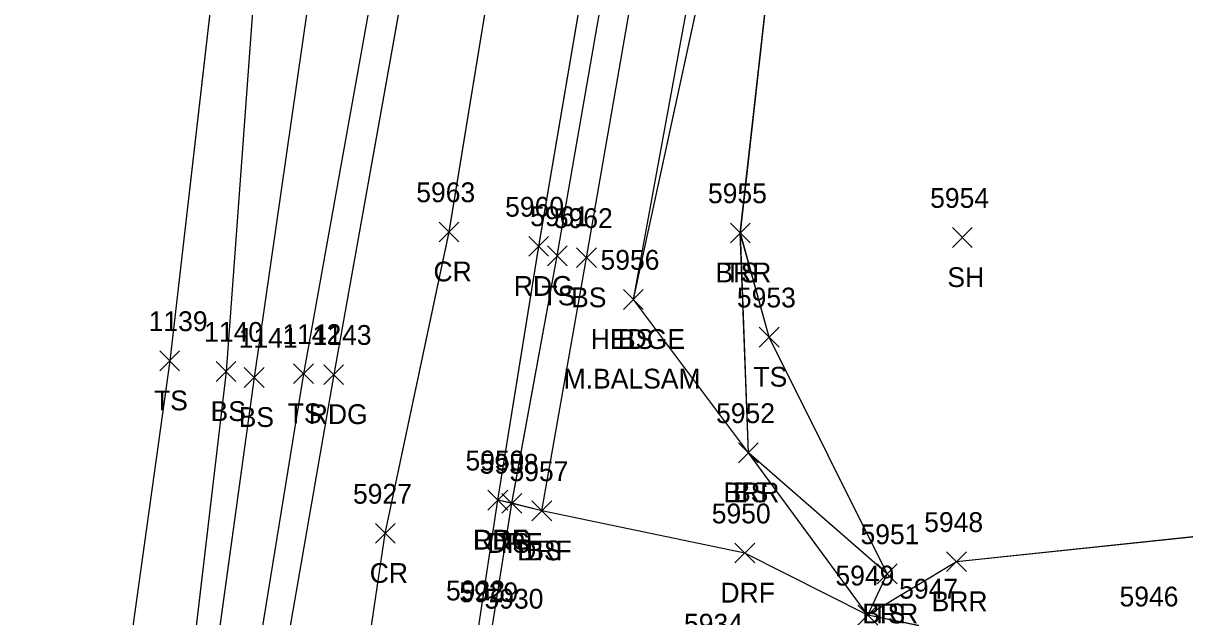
# Model space of a CAD drawing. Extents: x 1554668 to 1563881, y 831386 to 834374.
# Drawn here: x 1561871.6 to 1561988.8, y 833935.7 to 833995.6 of the extents above; entities that cross this region are included whole.
import ezdxf

# ---------------------------------------------------------------- set-up
doc = ezdxf.new("R2010")
doc.units = 0
for name, color, linetype in [('L_A', 7, 'Continuous'), ('L_C', 7, 'Continuous'), ('L_I', 7, 'Continuous'), ('L_TIC', 7, 'Continuous'), ('LABL', 7, 'Continuous'), ('LAHR', 7, 'Continuous'), ('LELB', 7, 'Continuous'), ('P_A', 7, 'Continuous'), ('P_I', 7, 'Continuous'), ('P_TIC', 7, 'Continuous'), ('PEU', 7, 'Continuous'), ('PRC', 7, 'Continuous'), ('R_A', 7, 'Continuous'), ('R_I', 7, 'Continuous'), ('R_TIC', 7, 'Continuous'), ('RDF', 7, 'Continuous')]:
    doc.layers.add(name, color=color, linetype=linetype)

msp = doc.modelspace()

# ---------------------------------------------------------------- linework, layer by layer
at = {"layer": 'L_TIC'}
for points in [[(1561942.96, 833973.43), (1561944.96, 833975.43)], [(1561944.96, 833973.43), (1561942.96, 833975.43)], [(1561942.96, 833973.43), (1561944.96, 833975.43)], [(1561944.96, 833973.43), (1561942.96, 833975.43)], [(1561965.38, 833972.96), (1561967.38, 833974.96)], [(1561967.38, 833972.96), (1561965.38, 833974.96)], [(1561924.49, 833971.11), (1561926.49, 833973.11)], [(1561926.49, 833971.11), (1561924.49, 833973.11)], [(1561927.44, 833970.92), (1561929.44, 833972.92)], [(1561929.44, 833970.92), (1561927.44, 833972.92)], [(1561932.17, 833966.71), (1561934.17, 833968.71)], [(1561934.17, 833966.71), (1561932.17, 833968.71)], [(1561932.17, 833966.71), (1561934.17, 833968.71)], [(1561934.17, 833966.71), (1561932.17, 833968.71)], [(1561945.88, 833962.9), (1561947.88, 833964.9)], [(1561947.88, 833962.9), (1561945.88, 833964.9)], [(1561885.36, 833960.51), (1561887.36, 833962.51)], [(1561887.36, 833960.51), (1561885.36, 833962.51)], [(1561891.04, 833959.43), (1561893.04, 833961.43)], [(1561893.04, 833959.43), (1561891.04, 833961.43)], [(1561893.88, 833958.83), (1561895.88, 833960.83)], [(1561895.88, 833958.83), (1561893.88, 833960.83)], [(1561898.86, 833959.21), (1561900.86, 833961.21)], [(1561900.86, 833959.21), (1561898.86, 833961.21)], [(1561943.78, 833951.22), (1561945.78, 833953.22)], [(1561945.78, 833951.22), (1561943.78, 833953.22)], [(1561943.78, 833951.22), (1561945.78, 833953.22)], [(1561945.78, 833951.22), (1561943.78, 833953.22)], [(1561919.9, 833946.11), (1561921.9, 833948.11)], [(1561921.9, 833946.11), (1561919.9, 833948.11)], [(1561922.92, 833945.36), (1561924.92, 833947.36)], [(1561924.92, 833945.36), (1561922.92, 833947.36)], [(1561964.79, 833940.22), (1561966.79, 833942.22)], [(1561966.79, 833940.22), (1561964.79, 833942.22)], [(1561957.79, 833938.99), (1561959.79, 833940.99)], [(1561959.79, 833938.99), (1561957.79, 833940.99)], [(1561957.79, 833938.99), (1561959.79, 833940.99)], [(1561959.79, 833938.99), (1561957.79, 833940.99)], [(1561955.84, 833934.82), (1561957.84, 833936.82)], [(1561957.84, 833934.82), (1561955.84, 833936.82)], [(1561955.84, 833934.82), (1561957.84, 833936.82)], [(1561957.84, 833934.82), (1561955.84, 833936.82)]]:
    msp.add_lwpolyline(points, dxfattribs=at)
at = {"layer": 'LABL'}
for points in [[(1562011.76, 833940.83), (1561992.19, 833943.99), (1561965.79, 833941.22), (1561956.84, 833935.82), (1561958.79, 833939.99), (1561944.78, 833952.22), (1561943.96, 833974.43), (1561948.54, 834015.15), (1561964.21, 834009.16), (1561972.84, 834001.4)], [(1562011.76, 833940.83), (1561992.19, 833943.98), (1561965.8, 833941.22), (1561956.84, 833935.82), (1561958.79, 833939.99), (1561944.79, 833952.22), (1561943.97, 833974.42), (1561948.54, 834015.15), (1561964.21, 834009.16), (1561972.84, 834001.4)], [(1562011.76, 833940.83), (1561992.19, 833943.98), (1561965.8, 833941.22), (1561956.84, 833935.82), (1561958.79, 833939.99), (1561944.79, 833952.22), (1561943.97, 833974.42), (1561948.54, 834015.15), (1561964.21, 834009.16), (1561972.84, 834001.4)], [(1562011.76, 833940.83), (1561992.19, 833943.98), (1561965.8, 833941.22), (1561956.84, 833935.82), (1561958.79, 833939.99), (1561944.79, 833952.22), (1561943.97, 833974.42), (1561948.54, 834015.15), (1561964.21, 834009.16), (1561972.84, 834001.4)]]:
    msp.add_lwpolyline(points, dxfattribs=at)
at = {"layer": 'LAHR'}
for points in [[(1561933.17, 833967.71), (1561943.92, 834017.24), (1561949.01, 834047.56), (1561954.45, 834088.78), (1561954.61, 834109.86), (1561954.6, 834110.79), (1561958.24, 834120.47)], [(1561933.17, 833967.71), (1561943.92, 834017.24), (1561949.01, 834047.56), (1561954.45, 834088.78), (1561954.61, 834109.86), (1561954.6, 834110.79), (1561958.24, 834120.47)], [(1561933.17, 833967.71), (1561943.92, 834017.24), (1561949.01, 834047.56), (1561954.45, 834088.78), (1561954.61, 834109.86), (1561954.6, 834110.79), (1561958.24, 834120.47)], [(1561933.17, 833967.71), (1561943.91, 834017.25), (1561949.02, 834047.56), (1561954.45, 834088.78), (1561954.61, 834109.86), (1561954.6, 834110.79), (1561958.24, 834120.47)]]:
    msp.add_lwpolyline(points, dxfattribs=at)
at = {"layer": 'LELB'}
for points in [[(1561890.59, 833773.39), (1561895.72, 833803.09), (1561903.04, 833845.23), (1561912.56, 833892.47), (1561912.52, 833900.11), (1561918.86, 833934.14), (1561920.9, 833947.12), (1561925.49, 833972.11), (1561933.78, 834019.88), (1561938.56, 834049.2), (1561945.5, 834091.94), (1561950.38, 834111.94), (1561953.62, 834113.33), (1561954.6, 834110.79), (1561955.4, 834117.28), (1561954.74, 834122.9), (1561961.07, 834128.41)], [(1561890.59, 833773.39), (1561895.72, 833803.09), (1561903.04, 833845.23), (1561912.56, 833892.47), (1561912.52, 833900.11), (1561918.86, 833934.14), (1561920.9, 833947.12), (1561925.49, 833972.11), (1561933.78, 834019.88), (1561938.56, 834049.2), (1561945.5, 834091.94), (1561950.38, 834111.94), (1561953.62, 834113.33), (1561954.6, 834110.79), (1561955.4, 834117.28), (1561954.74, 834122.9), (1561961.07, 834128.41)], [(1561890.59, 833773.39), (1561895.72, 833803.09), (1561903.04, 833845.23), (1561912.56, 833892.47), (1561912.52, 833900.11), (1561918.86, 833934.14), (1561920.9, 833947.12), (1561925.49, 833972.11), (1561933.78, 834019.88), (1561938.56, 834049.2), (1561945.5, 834091.94), (1561950.38, 834111.94), (1561953.62, 834113.33), (1561954.6, 834110.79), (1561955.4, 834117.28), (1561954.74, 834122.9), (1561961.07, 834128.41)], [(1561890.59, 833773.39), (1561895.72, 833803.08), (1561903.04, 833845.23), (1561912.56, 833892.47), (1561912.52, 833900.11), (1561918.86, 833934.13), (1561920.9, 833947.11), (1561925.49, 833972.11), (1561933.78, 834019.88), (1561938.56, 834049.2), (1561945.51, 834091.94), (1561950.38, 834111.94), (1561953.62, 834113.33), (1561954.6, 834110.79), (1561955.4, 834117.28), (1561954.73, 834122.9), (1561961.07, 834128.41)], [(1561923.92, 833946.36), (1561928.44, 833971.92), (1561936.65, 834019.21), (1561937.56, 834020.45), (1561941.76, 834048.64), (1561947.35, 834092.26), (1561953.88, 834111.21), (1561953.62, 834113.33), (1561951.9, 834118.24), (1561953.54, 834128.25)], [(1561923.92, 833946.36), (1561928.44, 833971.92), (1561936.65, 834019.21), (1561937.56, 834020.45), (1561941.76, 834048.64), (1561947.35, 834092.26), (1561953.88, 834111.21), (1561953.62, 834113.33), (1561951.9, 834118.24), (1561953.54, 834128.25)], [(1561923.92, 833946.36), (1561928.44, 833971.92), (1561936.65, 834019.21), (1561937.56, 834020.45), (1561941.76, 834048.64), (1561947.35, 834092.26), (1561953.88, 834111.21), (1561953.62, 834113.33), (1561951.9, 834118.24), (1561953.54, 834128.25)], [(1561923.92, 833946.36), (1561928.44, 833971.92), (1561936.65, 834019.21), (1561937.55, 834020.45), (1561941.75, 834048.64), (1561947.35, 834092.26), (1561953.88, 834111.21), (1561953.62, 834113.33), (1561951.9, 834118.24), (1561953.54, 834128.25)], [(1561956.84, 833935.82), (1561944.79, 833952.22), (1561933.17, 833967.71), (1561942.4, 834017.99), (1561945.38, 834048.68), (1561950.34, 834090.54), (1561954.61, 834109.86), (1561953.88, 834111.21)], [(1561956.84, 833935.82), (1561944.79, 833952.22), (1561933.17, 833967.71), (1561942.4, 834017.99), (1561945.38, 834048.68), (1561950.34, 834090.54), (1561954.61, 834109.86), (1561953.88, 834111.21)], [(1561956.84, 833935.82), (1561944.79, 833952.22), (1561933.17, 833967.71), (1561942.4, 834017.99), (1561945.38, 834048.68), (1561950.34, 834090.54), (1561954.61, 834109.86), (1561953.88, 834111.21)], [(1561956.84, 833935.82), (1561944.78, 833952.22), (1561933.17, 833967.71), (1561942.4, 834017.99), (1561945.38, 834048.68), (1561950.34, 834090.54), (1561954.61, 834109.86), (1561953.88, 834111.21)], [(1561815.74, 834086.46), (1561830.54, 834078.7), (1561857.36, 834066.17), (1561882.7, 834039.77), (1561887.42, 834039.12), (1561893.22, 834026.09), (1561901.9, 834008.43), (1561894.88, 833959.83), (1561888.21, 833911.57), (1561878.88, 833861.26), (1561873.84, 833826.24), (1561871.32, 833811.79), (1561866.2, 833788.52), (1561864.7, 833787.61), (1561863.71, 833789.64)], [(1561815.74, 834086.46), (1561831.97, 834080.43), (1561858.23, 834067.96), (1561883.25, 834047.53), (1561891.65, 834042.46), (1561901.6, 834025.45), (1561908.82, 834010.15), (1561899.86, 833960.21), (1561892.01, 833911.96), (1561883.18, 833863.91), (1561875.73, 833824.99), (1561873.41, 833811.32), (1561868.97, 833788.78), (1561866.02, 833786.68), (1561862.5, 833787.34), (1561864.02, 833802.29)], [(1561815.74, 834086.46), (1561830.54, 834078.7), (1561857.36, 834066.17), (1561882.7, 834039.77), (1561887.42, 834039.12), (1561893.22, 834026.09), (1561901.9, 834008.43), (1561894.88, 833959.83), (1561888.21, 833911.57), (1561878.88, 833861.26), (1561873.84, 833826.24), (1561871.32, 833811.79), (1561866.2, 833788.52), (1561864.7, 833787.61), (1561863.71, 833789.64)], [(1561815.74, 834086.46), (1561831.97, 834080.43), (1561858.23, 834067.96), (1561883.25, 834047.53), (1561891.65, 834042.46), (1561901.6, 834025.45), (1561908.82, 834010.15), (1561899.86, 833960.21), (1561892.01, 833911.96), (1561883.18, 833863.91), (1561875.73, 833824.99), (1561873.41, 833811.32), (1561868.97, 833788.78), (1561866.02, 833786.68), (1561862.5, 833787.34), (1561864.02, 833802.29)], [(1561815.74, 834086.46), (1561830.54, 834078.7), (1561857.36, 834066.17), (1561882.7, 834039.77), (1561887.42, 834039.12), (1561893.22, 834026.09), (1561901.9, 834008.43), (1561894.88, 833959.83), (1561888.21, 833911.57), (1561878.88, 833861.26), (1561873.84, 833826.24), (1561871.32, 833811.79), (1561866.2, 833788.52), (1561864.7, 833787.61), (1561863.71, 833789.64)], [(1561815.74, 834086.46), (1561831.97, 834080.43), (1561858.23, 834067.96), (1561883.25, 834047.53), (1561891.65, 834042.46), (1561901.6, 834025.45), (1561908.82, 834010.15), (1561899.86, 833960.21), (1561892.01, 833911.96), (1561883.18, 833863.91), (1561875.73, 833824.99), (1561873.41, 833811.32), (1561868.97, 833788.78), (1561866.02, 833786.68), (1561862.5, 833787.34), (1561864.02, 833802.29)], [(1561815.74, 834086.46), (1561830.54, 834078.7), (1561857.37, 834066.17), (1561882.7, 834039.77), (1561887.42, 834039.12), (1561893.22, 834026.09), (1561901.9, 834008.43), (1561894.88, 833959.83), (1561888.22, 833911.56), (1561878.88, 833861.26), (1561873.84, 833826.25), (1561871.32, 833811.8), (1561866.2, 833788.52), (1561864.7, 833787.61), (1561863.71, 833789.64)], [(1561815.74, 834086.46), (1561831.97, 834080.43), (1561858.23, 834067.96), (1561883.25, 834047.53), (1561891.65, 834042.46), (1561901.6, 834025.45), (1561908.82, 834010.15), (1561899.86, 833960.21), (1561892.01, 833911.96), (1561883.18, 833863.91), (1561875.73, 833824.99), (1561873.41, 833811.33), (1561868.97, 833788.78), (1561866.02, 833786.68), (1561862.5, 833787.34), (1561864.02, 833802.28)], [(1561853.22, 834063.56), (1561878.87, 834036.97), (1561887.19, 834023.31), (1561895.32, 834005.06), (1561892.04, 833960.44), (1561886.33, 833911.87), (1561875.09, 833862.64), (1561871.37, 833827.19), (1561868.33, 833813.19), (1561863.71, 833789.64)], [(1561853.22, 834063.56), (1561877.74, 834034.87), (1561883, 834019.83), (1561891.11, 834002.8), (1561886.36, 833961.51), (1561879.68, 833913.48), (1561869.91, 833864.41), (1561866.18, 833828.25), (1561865.19, 833815.47), (1561863.21, 833805.57), (1561864.02, 833802.29)], [(1561853.22, 834063.56), (1561878.87, 834036.97), (1561887.19, 834023.31), (1561895.32, 834005.06), (1561892.04, 833960.44), (1561886.33, 833911.87), (1561875.09, 833862.64), (1561871.37, 833827.19), (1561868.33, 833813.19), (1561863.71, 833789.64)], [(1561853.22, 834063.56), (1561877.74, 834034.87), (1561883, 834019.83), (1561891.11, 834002.8), (1561886.36, 833961.51), (1561879.68, 833913.48), (1561869.91, 833864.41), (1561866.18, 833828.25), (1561865.19, 833815.47), (1561863.21, 833805.57), (1561864.02, 833802.29)], [(1561853.22, 834063.56), (1561878.87, 834036.97), (1561887.19, 834023.31), (1561895.32, 834005.06), (1561892.04, 833960.44), (1561886.33, 833911.87), (1561875.09, 833862.64), (1561871.37, 833827.19), (1561868.33, 833813.19), (1561863.71, 833789.64)], [(1561853.22, 834063.56), (1561877.74, 834034.87), (1561883, 834019.83), (1561891.11, 834002.8), (1561886.36, 833961.51), (1561879.68, 833913.48), (1561869.91, 833864.41), (1561866.18, 833828.25), (1561865.19, 833815.47), (1561863.21, 833805.57), (1561864.02, 833802.29)], [(1561853.22, 834063.56), (1561878.87, 834036.97), (1561887.19, 834023.32), (1561895.32, 834005.06), (1561892.04, 833960.43), (1561886.33, 833911.86), (1561875.09, 833862.64), (1561871.37, 833827.19), (1561868.33, 833813.19), (1561863.71, 833789.64)], [(1561853.22, 834063.56), (1561877.74, 834034.87), (1561883, 834019.83), (1561891.11, 834002.81), (1561886.36, 833961.51), (1561879.68, 833913.48), (1561869.91, 833864.41), (1561866.18, 833828.24), (1561865.19, 833815.47), (1561863.21, 833805.57), (1561864.02, 833802.28)], [(1561958.79, 833939.99), (1561946.88, 833963.9), (1561943.96, 833974.43)], [(1561958.79, 833939.99), (1561946.89, 833963.9), (1561943.97, 833974.42)], [(1561958.79, 833939.99), (1561946.89, 833963.9), (1561943.97, 833974.42)], [(1561958.79, 833939.99), (1561946.89, 833963.9), (1561943.97, 833974.42)]]:
    msp.add_lwpolyline(points, dxfattribs=at)
at = {"layer": 'P_TIC'}
for points in [[(1561913.56, 833973.53), (1561915.56, 833975.53)], [(1561915.56, 833973.53), (1561913.56, 833975.53)], [(1561922.61, 833972.07), (1561924.61, 833974.07)], [(1561924.61, 833972.07), (1561922.61, 833974.07)], [(1561901.91, 833959.12), (1561903.91, 833961.12)], [(1561903.91, 833959.12), (1561901.91, 833961.12)], [(1561918.49, 833946.44), (1561920.49, 833948.44)], [(1561920.49, 833946.44), (1561918.49, 833948.44)], [(1561907.12, 833943.08), (1561909.12, 833945.08)], [(1561909.12, 833943.08), (1561907.12, 833945.08)]]:
    msp.add_lwpolyline(points, dxfattribs=at)
at = {"layer": 'PEU'}
for points in [[(1561919.94, 834298.23), (1561943.28, 834270.95), (1561951.49, 834242.5), (1561947.43, 834199.98), (1561938.33, 834160.95), (1561930.99, 834108.21), (1561926.2, 834084.15), (1561918.63, 834048.82), (1561911.3, 834007.02), (1561902.91, 833960.12), (1561894.33, 833910.71), (1561885.39, 833863.27), (1561878.37, 833822.84), (1561871.83, 833787.48), (1561866.71, 833759.34), (1561861.91, 833735.82)], [(1561919.94, 834298.23), (1561943.28, 834270.95), (1561951.49, 834242.5), (1561947.43, 834199.98), (1561938.33, 834160.95), (1561930.99, 834108.21), (1561926.2, 834084.15), (1561918.63, 834048.82), (1561911.3, 834007.02), (1561902.91, 833960.12), (1561894.33, 833910.71), (1561885.39, 833863.27), (1561878.37, 833822.84), (1561871.83, 833787.48), (1561866.71, 833759.34), (1561861.91, 833735.82)], [(1561919.94, 834298.23), (1561943.28, 834270.95), (1561951.49, 834242.5), (1561947.43, 834199.98), (1561938.33, 834160.95), (1561930.99, 834108.21), (1561926.2, 834084.15), (1561918.63, 834048.82), (1561911.3, 834007.02), (1561902.91, 833960.12), (1561894.33, 833910.71), (1561885.39, 833863.27), (1561878.37, 833822.84), (1561871.83, 833787.48), (1561866.71, 833759.34), (1561861.91, 833735.82)], [(1561919.94, 834298.23), (1561943.28, 834270.95), (1561951.49, 834242.5), (1561947.43, 834199.98), (1561938.34, 834160.95), (1561930.99, 834108.21), (1561926.2, 834084.15), (1561918.63, 834048.82), (1561911.3, 834007.01), (1561902.91, 833960.12), (1561894.33, 833910.71), (1561885.39, 833863.26), (1561878.37, 833822.84), (1561871.83, 833787.48), (1561866.71, 833759.34), (1561861.91, 833735.82)], [(1561874.55, 833715.87), (1561887.48, 833772.58), (1561893.31, 833803.99), (1561901.36, 833845.45), (1561909.68, 833892.69), (1561910.73, 833900.62), (1561917.51, 833934.31), (1561919.49, 833947.44), (1561923.61, 833973.08), (1561931.59, 834020), (1561935.39, 834050.31), (1561943.17, 834094.38), (1561948.42, 834126.58), (1561953.28, 834146.88), (1561956.68, 834158.88)], [(1561874.55, 833715.87), (1561887.48, 833772.58), (1561893.31, 833803.99), (1561901.36, 833845.45), (1561909.68, 833892.69), (1561910.73, 833900.62), (1561917.51, 833934.31), (1561919.49, 833947.44), (1561923.61, 833973.08), (1561931.59, 834020), (1561935.39, 834050.31), (1561943.17, 834094.38), (1561948.42, 834126.58), (1561953.28, 834146.88), (1561956.68, 834158.88)], [(1561874.55, 833715.87), (1561887.48, 833772.58), (1561893.31, 833803.99), (1561901.36, 833845.45), (1561909.68, 833892.69), (1561910.73, 833900.62), (1561917.51, 833934.31), (1561919.49, 833947.44), (1561923.61, 833973.08), (1561931.59, 834020), (1561935.39, 834050.31), (1561943.17, 834094.38), (1561948.42, 834126.58), (1561953.28, 834146.88), (1561956.68, 834158.88)], [(1561874.55, 833715.88), (1561887.48, 833772.58), (1561893.31, 833803.99), (1561901.36, 833845.45), (1561909.68, 833892.69), (1561910.73, 833900.62), (1561917.51, 833934.31), (1561919.49, 833947.44), (1561923.61, 833973.07), (1561931.59, 834020), (1561935.39, 834050.31), (1561943.17, 834094.38), (1561948.42, 834126.57), (1561953.28, 834146.88), (1561956.68, 834158.88)]]:
    msp.add_lwpolyline(points, dxfattribs=at)
at = {"layer": 'PRC'}
for points in [[(1561800.21, 833371.54), (1561806.44, 833405.19), (1561812.66, 833434.93), (1561820.13, 833472.18), (1561827.53, 833505.74), (1561836.94, 833558.6), (1561848.04, 833617.29), (1561858.18, 833669.76), (1561866.96, 833717.24), (1561878.61, 833773.78), (1561885.02, 833806.83), (1561891.66, 833847.81), (1561899.78, 833893.72), (1561902.02, 833902.92), (1561908.12, 833944.07), (1561914.56, 833974.52), (1561922.25, 834021.37), (1561927.37, 834052.03), (1561935.21, 834096), (1561945.53, 834150.77)], [(1561800.21, 833371.54), (1561806.44, 833405.19), (1561812.66, 833434.93), (1561820.13, 833472.18), (1561827.53, 833505.74), (1561836.94, 833558.6), (1561848.04, 833617.29), (1561858.18, 833669.76), (1561866.96, 833717.24), (1561878.61, 833773.78), (1561885.02, 833806.83), (1561891.66, 833847.81), (1561899.78, 833893.72), (1561902.02, 833902.92), (1561908.12, 833944.07), (1561914.56, 833974.52), (1561922.25, 834021.37), (1561927.37, 834052.03), (1561935.21, 834096), (1561945.53, 834150.77)], [(1561800.21, 833371.54), (1561806.44, 833405.19), (1561812.66, 833434.93), (1561820.13, 833472.18), (1561827.53, 833505.74), (1561836.94, 833558.6), (1561848.04, 833617.29), (1561858.18, 833669.76), (1561866.96, 833717.24), (1561878.61, 833773.78), (1561885.02, 833806.83), (1561891.66, 833847.81), (1561899.78, 833893.72), (1561902.02, 833902.92), (1561908.12, 833944.07), (1561914.56, 833974.52), (1561922.25, 834021.37), (1561927.37, 834052.03), (1561935.21, 834096), (1561945.53, 834150.77)], [(1561800.21, 833371.54), (1561806.44, 833405.19), (1561812.65, 833434.93), (1561820.13, 833472.19), (1561827.53, 833505.75), (1561836.94, 833558.61), (1561848.04, 833617.29), (1561858.18, 833669.76), (1561866.96, 833717.25), (1561878.6, 833773.78), (1561885.02, 833806.83), (1561891.66, 833847.81), (1561899.78, 833893.72), (1561902.02, 833902.92), (1561908.12, 833944.08), (1561914.56, 833974.53), (1561922.25, 834021.37), (1561927.37, 834052.03), (1561935.21, 834096), (1561945.53, 834150.77)]]:
    msp.add_lwpolyline(points, dxfattribs=at)
at = {"layer": 'R_TIC'}
for points in [[(1561918.49, 833946.44), (1561920.49, 833948.44)], [(1561920.49, 833946.44), (1561918.49, 833948.44)], [(1561919.9, 833946.11), (1561921.9, 833948.11)], [(1561921.9, 833946.11), (1561919.9, 833948.11)], [(1561922.92, 833945.36), (1561924.92, 833947.36)], [(1561924.92, 833945.36), (1561922.92, 833947.36)], [(1561943.42, 833941.09), (1561945.42, 833943.09)], [(1561945.42, 833941.09), (1561943.42, 833943.09)], [(1561955.84, 833934.82), (1561957.84, 833936.82)], [(1561957.84, 833934.82), (1561955.84, 833936.82)]]:
    msp.add_lwpolyline(points, dxfattribs=at)
at = {"layer": 'RDF'}
for points in [[(1561985.57, 833933.7), (1561963.27, 833934.5), (1561956.84, 833935.82), (1561944.43, 833942.09), (1561923.92, 833946.36), (1561920.9, 833947.12), (1561919.49, 833947.44)], [(1561985.57, 833933.7), (1561963.27, 833934.5), (1561956.84, 833935.82), (1561944.43, 833942.09), (1561923.92, 833946.36), (1561920.9, 833947.12), (1561919.49, 833947.44)], [(1561985.57, 833933.7), (1561963.27, 833934.5), (1561956.84, 833935.82), (1561944.43, 833942.09), (1561923.92, 833946.36), (1561920.9, 833947.12), (1561919.49, 833947.44)], [(1561985.56, 833933.7), (1561963.26, 833934.49), (1561956.84, 833935.82), (1561944.42, 833942.09), (1561923.92, 833946.36), (1561920.9, 833947.11), (1561919.49, 833947.44)]]:
    msp.add_lwpolyline(points, dxfattribs=at)

# ---------------------------------------------------------------- texts
at = {"layer": 'L_A'}
for s, p in [('BRR', (1561941.45, 833969.43)), ('TS', (1561942.37, 833969.43)), ('SH', (1561964.87, 833968.96)), ('TS', (1561923.9, 833967.11)), ('BS', (1561926.88, 833966.92)), ('HEDGE', (1561928.87, 833962.71)), ('BS', (1561931.61, 833962.71)), ('TS', (1561945.29, 833958.9)), ('TS', (1561884.77, 833956.51)), ('BS', (1561890.48, 833955.43)), ('TS', (1561898.27, 833955.21)), ('BS', (1561893.32, 833954.83)), ('BRR', (1561942.27, 833947.22)), ('BS', (1561943.23, 833947.22)), ('TS', (1561919.31, 833942.11)), ('BS', (1561922.36, 833941.36)), ('BRR', (1561963.28, 833936.22)), ('BRR', (1561956.28, 833934.99)), ('TS', (1561957.2, 833934.99))]:
    msp.add_text(s, height=2, dxfattribs=at).set_placement(p)
at = {"layer": 'L_C'}
msp.add_text('M.BALSAM', height=2, dxfattribs=at).set_placement((1561926.13, 833958.71))
at = {"layer": 'L_I'}
for s, p in [('5955', (1561940.7, 833977.43)), ('5955', (1561940.7, 833977.43)), ('5954', (1561963.13, 833976.96)), ('5961', (1561922.75, 833975.11)), ('5962', (1561925.14, 833974.92)), ('5956', (1561929.85, 833970.71)), ('5956', (1561929.85, 833970.71)), ('5953', (1561943.62, 833966.9)), ('1139', (1561884.23, 833964.51)), ('1140', (1561889.83, 833963.43)), ('1141', (1561893.32, 833962.83)), ('1142', (1561897.73, 833963.21)), ('5952', (1561941.52, 833955.22)), ('5952', (1561941.52, 833955.22)), ('5958', (1561917.64, 833950.11)), ('5957', (1561920.66, 833949.36)), ('5948', (1561962.53, 833944.22)), ('5951', (1561956.1, 833942.99)), ('5951', (1561956.1, 833942.99)), ('5949', (1561953.57, 833938.82)), ('5949', (1561953.57, 833938.82)), ('5929', (1561915.59, 833937.13)), ('5930', (1561918.14, 833936.48))]:
    msp.add_text(s, height=2, dxfattribs=at).set_placement(p)
at = {"layer": 'P_A'}
for s, p in [('CR', (1561912.99, 833969.53)), ('RDG', (1561921.1, 833968.07)), ('RDG', (1561900.4, 833955.12)), ('RDG', (1561916.97, 833942.44)), ('CR', (1561906.55, 833939.08))]:
    msp.add_text(s, height=2, dxfattribs=at).set_placement(p)
at = {"layer": 'P_I'}
for s, p in [('5963', (1561911.25, 833977.53)), ('5960', (1561920.22, 833976.07)), ('1143', (1561900.78, 833963.12)), ('5959', (1561916.22, 833950.44)), ('5927', (1561904.86, 833947.08)), ('5928', (1561914.25, 833937.31))]:
    msp.add_text(s, height=2, dxfattribs=at).set_placement(p)
at = {"layer": 'R_A'}
for p in [(1561917.02, 833942.44), (1561918.44, 833942.11), (1561921.45, 833941.36), (1561941.96, 833937.09)]:
    msp.add_text('DRF', height=2, dxfattribs=at).set_placement(p)
at = {"layer": 'R_I'}
for s, p in [('5959', (1561916.22, 833950.44)), ('5958', (1561917.64, 833950.11)), ('5957', (1561920.66, 833949.36)), ('5950', (1561941.08, 833945.09)), ('5949', (1561953.57, 833938.82)), ('5928', (1561914.25, 833937.31)), ('5929', (1561915.59, 833937.13)), ('5930', (1561918.14, 833936.48)), ('5947', (1561960, 833937.49)), ('5946', (1561982.25, 833936.7)), ('5934', (1561938.28, 833933.96))]:
    msp.add_text(s, height=2, dxfattribs=at).set_placement(p)

doc.saveas('drawing.dxf')
